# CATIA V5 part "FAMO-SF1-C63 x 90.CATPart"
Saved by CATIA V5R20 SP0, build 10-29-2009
Part number: FAMO-SF1-C63 x 90
Definition: NONE
Nomenclature: FAMO-SF1-C63 x 90
Source: Unknown
Description: FAMO-SF1-C63 x 90
Bounding box of the stored display mesh (mm): x -42 to 48, y -46 to 46, z -46 to 46
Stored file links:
  C:\Users\Utente\Desktop\IO LAVORO\3D X SITO CF\X SITO\FAMO\FAMO-SF1-C63 x 90.CATPart

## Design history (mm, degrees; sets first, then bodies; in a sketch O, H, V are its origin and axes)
Body1 "FAMO-SF1-C63 x 90" (main body)
  Solid1: solid without history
